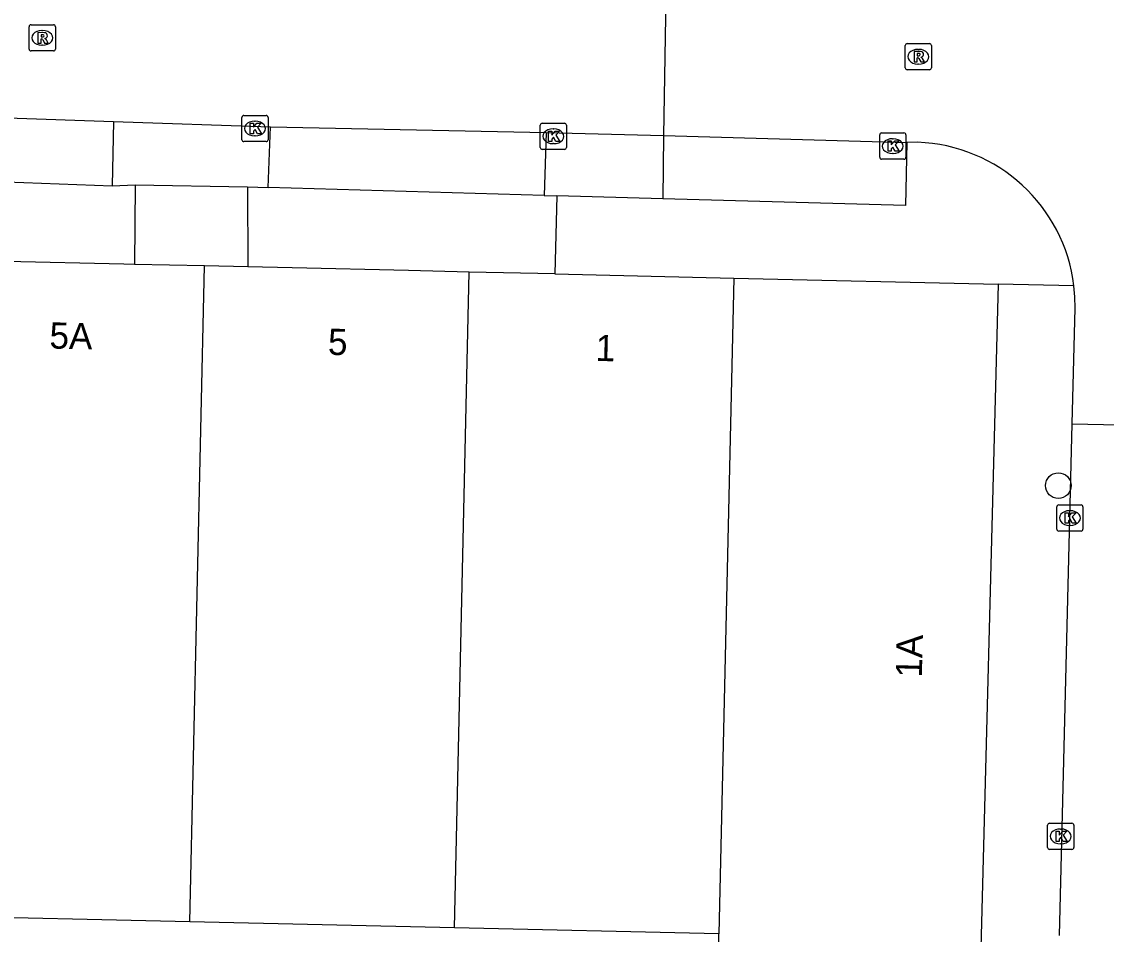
# Model space of a CAD drawing. Extents: x 162082 to 163393, y 388091 to 388632.
# Drawn here: x 162448.47 to 162489.83, y 388163.79 to 388198.6 of the extents above; entities that cross this region are included whole.
import ezdxf

# ---------------------------------------------------------------- set-up
doc = ezdxf.new("R2010")
doc.units = 0
for name, color, linetype in [('IMGEO_Boom', 7, 'Continuous'), ('IMGEO_Kolk', 7, 'Continuous'), ('IMGEO_Pand', 7, 'Continuous'), ('IMGEO_Pand_nummerreeks', 7, 'Continuous'), ('IMGEO_Parkeervlak_open', 7, 'Continuous'), ('IMGEO_Rijbaan_lokaal_open', 7, 'Continuous'), ('IMGEO_Rioolput', 7, 'Continuous'), ('IMGEO_Voetpad_open', 7, 'Continuous')]:
    doc.layers.add(name, color=color, linetype=linetype)

msp = doc.modelspace()

# ---------------------------------------------------------------- linework, layer by layer
at = {"layer": 'IMGEO_Boom'}
msp.add_circle((162488.002, 388180.905), 0.489, dxfattribs=at)
at = {"layer": 'IMGEO_Kolk'}
for p, q in [((162456.863, 388194.101), (162456.863, 388194.953)), ((162456.938, 388195.027), (162457.79, 388195.027)), ((162457.351, 388194.807), (162457.376, 388194.807)), ((162457.864, 388194.953), (162457.864, 388194.101)), ((162468.243, 388193.804), (162468.243, 388194.656)), ((162468.318, 388194.73), (162469.17, 388194.73)), ((162468.731, 388194.51), (162468.756, 388194.51)), ((162469.244, 388194.656), (162469.244, 388193.804)), ((162481.264, 388194.358), (162482.116, 388194.358)), ((162457.79, 388194.027), (162456.938, 388194.027)), ((162457.374, 388194.247), (162457.349, 388194.247)), ((162468.754, 388193.95), (162468.729, 388193.95)), ((162481.189, 388193.432), (162481.189, 388194.284)), ((162481.677, 388194.138), (162481.702, 388194.138)), ((162482.19, 388194.284), (162482.19, 388193.432)), ((162469.17, 388193.73), (162468.318, 388193.73)), ((162481.7, 388193.578), (162481.675, 388193.578)), ((162482.116, 388193.358), (162481.264, 388193.358)), ((162487.942, 388179.242), (162487.942, 388180.094)), ((162488.017, 388180.168), (162488.869, 388180.168)), ((162488.43, 388179.948), (162488.455, 388179.948)), ((162488.943, 388180.094), (162488.943, 388179.242)), ((162488.869, 388179.168), (162488.017, 388179.168)), ((162488.453, 388179.388), (162488.428, 388179.388)), ((162487.595, 388167.099), (162487.595, 388167.951)), ((162487.67, 388168.025), (162488.522, 388168.025)), ((162488.596, 388167.951), (162488.596, 388167.099)), ((162488.083, 388167.805), (162488.108, 388167.805)), ((162488.106, 388167.245), (162488.081, 388167.245)), ((162488.522, 388167.025), (162487.67, 388167.025))]:
    msp.add_line(p, q, dxfattribs=at)
for points in [[(162456.863, 388194.101), (162456.863, 388194.953)], [(162456.938, 388195.027), (162457.79, 388195.027)], [(162457.864, 388194.953), (162457.864, 388194.101)], [(162457.184, 388194.727), (162457.307, 388194.727), (162457.307, 388194.576), (162457.437, 388194.727), (162457.601, 388194.727), (162457.455, 388194.576), (162457.608, 388194.327), (162457.456, 388194.327), (162457.371, 388194.491), (162457.307, 388194.424), (162457.307, 388194.327), (162457.184, 388194.327), (162457.184, 388194.727)], [(162468.243, 388193.804), (162468.243, 388194.656)], [(162468.318, 388194.73), (162469.17, 388194.73)], [(162468.564, 388194.43), (162468.687, 388194.43), (162468.687, 388194.279), (162468.817, 388194.43), (162468.981, 388194.43), (162468.835, 388194.279), (162468.988, 388194.03), (162468.836, 388194.03), (162468.751, 388194.194), (162468.687, 388194.127), (162468.687, 388194.03), (162468.564, 388194.03), (162468.564, 388194.43)], [(162469.244, 388194.656), (162469.244, 388193.804)], [(162481.264, 388194.358), (162482.116, 388194.358)], [(162457.79, 388194.027), (162456.938, 388194.027)], [(162481.189, 388193.432), (162481.189, 388194.284)], [(162481.51, 388194.058), (162481.633, 388194.058), (162481.633, 388193.907), (162481.763, 388194.058), (162481.927, 388194.058), (162481.781, 388193.907), (162481.934, 388193.658), (162481.782, 388193.658), (162481.697, 388193.822), (162481.633, 388193.755), (162481.633, 388193.658), (162481.51, 388193.658), (162481.51, 388194.058)], [(162482.19, 388194.284), (162482.19, 388193.432)], [(162469.17, 388193.73), (162468.318, 388193.73)], [(162482.116, 388193.358), (162481.264, 388193.358)], [(162487.942, 388179.242), (162487.942, 388180.094)], [(162488.017, 388180.168), (162488.869, 388180.168)], [(162488.263, 388179.868), (162488.386, 388179.868), (162488.386, 388179.717), (162488.516, 388179.868), (162488.68, 388179.868), (162488.534, 388179.717), (162488.687, 388179.468), (162488.535, 388179.468), (162488.45, 388179.632), (162488.386, 388179.565), (162488.386, 388179.468), (162488.263, 388179.468), (162488.263, 388179.868)], [(162488.943, 388180.094), (162488.943, 388179.242)], [(162488.869, 388179.168), (162488.017, 388179.168)], [(162487.595, 388167.099), (162487.595, 388167.951)], [(162487.67, 388168.025), (162488.522, 388168.025)], [(162488.596, 388167.951), (162488.596, 388167.099)], [(162487.916, 388167.725), (162488.039, 388167.725), (162488.039, 388167.574), (162488.169, 388167.725), (162488.333, 388167.725), (162488.187, 388167.574), (162488.34, 388167.325), (162488.188, 388167.325), (162488.103, 388167.489), (162488.039, 388167.422), (162488.039, 388167.325), (162487.916, 388167.325), (162487.916, 388167.725)], [(162488.522, 388167.025), (162487.67, 388167.025)]]:
    msp.add_lwpolyline(points, dxfattribs=at)
for centre, start, end in [((162456.94, 388194.951), 91.552, 178.448), ((162456.94, 388194.951), 91.552, 178.448), ((162457.788, 388194.951), 1.552, 88.448), ((162457.788, 388194.951), 1.552, 88.448), ((162468.32, 388194.654), 91.552, 178.448), ((162468.32, 388194.654), 91.552, 178.448), ((162469.168, 388194.654), 1.552, 88.448), ((162469.168, 388194.654), 1.552, 88.448), ((162481.266, 388194.282), 91.552, 178.448), ((162481.266, 388194.282), 91.552, 178.448), ((162482.114, 388194.282), 1.552, 88.448), ((162482.114, 388194.282), 1.552, 88.448), ((162456.94, 388194.103), 181.552, 268.448), ((162456.94, 388194.103), 181.552, 268.448), ((162457.788, 388194.103), 271.552, 358.448), ((162457.788, 388194.103), 271.552, 358.448), ((162468.32, 388193.806), 181.552, 268.448), ((162468.32, 388193.806), 181.552, 268.448), ((162469.168, 388193.806), 271.552, 358.448), ((162469.168, 388193.806), 271.552, 358.448), ((162481.266, 388193.434), 181.552, 268.448), ((162481.266, 388193.434), 181.552, 268.448), ((162482.114, 388193.434), 271.552, 358.448), ((162482.114, 388193.434), 271.552, 358.448), ((162488.019, 388180.092), 91.552, 178.448), ((162488.019, 388180.092), 91.552, 178.448), ((162488.867, 388180.092), 1.552, 88.448), ((162488.867, 388180.092), 1.552, 88.448), ((162488.019, 388179.244), 181.552, 268.448), ((162488.019, 388179.244), 181.552, 268.448), ((162488.867, 388179.244), 271.552, 358.448), ((162488.867, 388179.244), 271.552, 358.448), ((162487.672, 388167.949), 91.552, 178.448), ((162487.672, 388167.949), 91.552, 178.448), ((162488.52, 388167.949), 1.552, 88.448), ((162488.52, 388167.949), 1.552, 88.448), ((162487.672, 388167.101), 181.552, 268.448), ((162487.672, 388167.101), 181.552, 268.448), ((162488.52, 388167.101), 271.552, 358.448), ((162488.52, 388167.101), 271.552, 358.448)]:
    msp.add_arc(centre, 0.0765, start, end, dxfattribs=at)
for centre, major_axis, ratio, start_param, end_param in [((162457.35, 388194.527), (-0.387, 0.002), 0.722429, 4.712389, 7.853982), ((162457.375, 388194.527), (-0.39, 0.002), 0.717154, 1.570796, 4.712389), ((162468.73, 388194.23), (-0.387, 0.002), 0.722429, 4.712389, 7.853982), ((162468.755, 388194.23), (-0.39, 0.002), 0.717154, 1.570796, 4.712389), ((162481.676, 388193.858), (-0.387, 0.002), 0.722429, 4.712389, 7.853982), ((162481.701, 388193.858), (-0.39, 0.002), 0.717154, 1.570796, 4.712389), ((162488.429, 388179.668), (-0.387, 0.002), 0.722429, 4.712389, 7.853982), ((162488.454, 388179.668), (-0.39, 0.002), 0.717154, 1.570796, 4.712389), ((162488.082, 388167.525), (-0.387, 0.002), 0.722429, 4.712389, 7.853982), ((162488.107, 388167.525), (-0.39, 0.002), 0.717154, 1.570796, 4.712389)]:
    msp.add_ellipse(centre, major_axis=major_axis, ratio=ratio, start_param=start_param, end_param=end_param, dxfattribs=at)
at = {"layer": 'IMGEO_Pand'}
for points in [[(162452.771, 388189.344), (162452.361, 388189.353), (162447.872, 388189.456), (162446.871, 388189.479)], [(162455.444, 388189.283), (162452.771, 388189.344)], [(162454.875, 388164.26), (162455.444, 388189.283)], [(162457.091, 388189.245), (162455.444, 388189.283)], [(162465.536, 388189.053), (162463.223, 388189.106), (162458.778, 388189.207), (162457.091, 388189.245)], [(162464.967, 388164.031), (162465.536, 388189.053)], [(162468.797, 388188.979), (162465.536, 388189.053)], [(162468.797, 388188.979), (162475.628, 388188.823)], [(162475.628, 388188.823), (162475.059, 388163.801)], [(162475.628, 388188.823), (162485.703, 388188.593)], [(162485.703, 388188.593), (162484.964, 388159.853)], [(162454.875, 388164.26), (162444.783, 388164.49), (162444.873, 388168.421)], [(162464.967, 388164.031), (162454.875, 388164.26)], [(162475.059, 388163.801), (162464.967, 388164.031)], [(162484.964, 388159.853), (162479.966, 388159.982), (162474.998, 388160.11), (162475.059, 388163.801)]]:
    msp.add_lwpolyline(points, dxfattribs=at)
at = {"layer": 'IMGEO_Parkeervlak_open'}
msp.add_lwpolyline([(162472.938, 388194.261), (162472.925, 388191.851)], dxfattribs=at)
at = {"layer": 'IMGEO_Rijbaan_lokaal_open'}
for points in [[(162473.05, 388200.285), (162472.938, 388194.261)], [(162447.924, 388194.933), (162451.967, 388194.796)], [(162451.967, 388194.796), (162457.958, 388194.586)], [(162457.958, 388194.586), (162468.471, 388194.374)], [(162468.471, 388194.374), (162472.938, 388194.261)], [(162472.938, 388194.261), (162482.226, 388193.997)], [(162482.636, 388194.002), (162482.226, 388193.997)], [(162488.529, 388183.267), (162488.64, 388187.674), (162488.633, 388188.101), (162488.596, 388188.527)], [(162488.051, 388163.748), (162488.529, 388183.267)], [(162488.529, 388183.267), (162494.536, 388183.135)]]:
    msp.add_lwpolyline(points, dxfattribs=at)
msp.add_arc((162482.417, 388187.783), 6.223, 6.8699, 87.9875, dxfattribs=at)
at = {"layer": 'IMGEO_Rioolput'}
for p, q in [((162448.824, 388198.486), (162449.676, 388198.486)), ((162448.749, 388197.56), (162448.749, 388198.412)), ((162449.237, 388198.266), (162449.262, 388198.266)), ((162449.75, 388198.412), (162449.75, 388197.56)), ((162449.26, 388197.706), (162449.235, 388197.706)), ((162482.163, 388196.841), (162482.163, 388197.693)), ((162482.238, 388197.767), (162483.09, 388197.767)), ((162483.164, 388197.693), (162483.164, 388196.841)), ((162449.676, 388197.486), (162448.824, 388197.486)), ((162482.651, 388197.547), (162482.676, 388197.547)), ((162482.674, 388196.987), (162482.649, 388196.987)), ((162483.09, 388196.767), (162482.238, 388196.767))]:
    msp.add_line(p, q, dxfattribs=at)
for points in [[(162448.824, 388198.486), (162449.676, 388198.486)], [(162448.749, 388197.56), (162448.749, 388198.412)], [(162449.338, 388198.184), (162449.086, 388198.186), (162449.086, 388197.786)], [(162449.264, 388198.105), (162449.21, 388198.105), (162449.21, 388198.024)], [(162449.75, 388198.412), (162449.75, 388197.56)], [(162449.086, 388197.786), (162449.21, 388197.786), (162449.21, 388197.948), (162449.221, 388197.948)], [(162449.21, 388198.024), (162449.262, 388198.024)], [(162449.268, 388197.919), (162449.339, 388197.786), (162449.479, 388197.786), (162449.414, 388197.912)], [(162482.163, 388196.841), (162482.163, 388197.693)], [(162482.238, 388197.767), (162483.09, 388197.767)], [(162483.164, 388197.693), (162483.164, 388196.841)], [(162449.676, 388197.486), (162448.824, 388197.486)], [(162482.752, 388197.465), (162482.5, 388197.467), (162482.5, 388197.067)], [(162482.5, 388197.067), (162482.624, 388197.067), (162482.624, 388197.229), (162482.635, 388197.229)], [(162482.678, 388197.386), (162482.624, 388197.386), (162482.624, 388197.305)], [(162482.624, 388197.305), (162482.676, 388197.305)], [(162482.682, 388197.2), (162482.753, 388197.067), (162482.893, 388197.067), (162482.828, 388197.193)], [(162483.09, 388196.767), (162482.238, 388196.767)]]:
    msp.add_lwpolyline(points, dxfattribs=at)
for centre, radius, start, end in [((162448.826, 388198.41), 0.0765, 91.552, 178.448), ((162448.826, 388198.41), 0.0765, 91.552, 178.448), ((162449.674, 388198.41), 0.0765, 1.552, 88.448), ((162449.674, 388198.41), 0.0765, 1.552, 88.448), ((162449.27, 388198.009), 0.0964, 77.0061, 93.1865), ((162449.284, 388198.066), 0.0378, 276.6634, 79.6772), ((162449.337, 388198.074), 0.109, 350.3612, 89.416), ((162449.22, 388197.895), 0.0533, 26.0293, 88.6989), ((162449.246, 388198.213), 0.19, 274.7715, 282.9687), ((162449.335, 388198.074), 0.112, 277.5842, 350.9817), ((162449.319, 388197.859), 0.108, 29.5134, 73.7905), ((162482.24, 388197.691), 0.0765, 91.552, 178.448), ((162482.24, 388197.691), 0.0765, 91.552, 178.448), ((162483.088, 388197.691), 0.0765, 1.552, 88.448), ((162483.088, 388197.691), 0.0765, 1.552, 88.448), ((162448.826, 388197.562), 0.0765, 181.552, 268.448), ((162448.826, 388197.562), 0.0765, 181.552, 268.448), ((162449.674, 388197.562), 0.0765, 271.552, 358.448), ((162449.674, 388197.562), 0.0765, 271.552, 358.448), ((162482.634, 388197.176), 0.0533, 26.0293, 88.6989), ((162482.66, 388197.494), 0.19, 274.7715, 282.9687), ((162482.684, 388197.29), 0.0964, 77.0061, 93.1865), ((162482.698, 388197.347), 0.0378, 276.6634, 79.6772), ((162482.751, 388197.355), 0.109, 350.3612, 89.416), ((162482.749, 388197.355), 0.112, 277.5842, 350.9817), ((162482.733, 388197.14), 0.108, 29.5134, 73.7905), ((162482.24, 388196.843), 0.0765, 181.552, 268.448), ((162482.24, 388196.843), 0.0765, 181.552, 268.448), ((162483.088, 388196.843), 0.0765, 271.552, 358.448), ((162483.088, 388196.843), 0.0765, 271.552, 358.448)]:
    msp.add_arc(centre, radius, start, end, dxfattribs=at)
for centre, major_axis, ratio, start_param, end_param in [((162449.236, 388197.986), (-0.387, 0.002), 0.722429, 4.712389, 7.853982), ((162449.261, 388197.986), (-0.39, 0.002), 0.717154, 1.570796, 4.712389), ((162482.65, 388197.267), (-0.387, 0.002), 0.722429, 4.712389, 7.853982), ((162482.675, 388197.267), (-0.39, 0.002), 0.717154, 1.570796, 4.712389)]:
    msp.add_ellipse(centre, major_axis=major_axis, ratio=ratio, start_param=start_param, end_param=end_param, dxfattribs=at)
at = {"layer": 'IMGEO_Voetpad_open'}
for points in [[(162451.967, 388194.796), (162451.922, 388192.347)], [(162457.872, 388192.28), (162457.958, 388194.586)], [(162468.471, 388194.374), (162468.393, 388191.974)], [(162482.226, 388193.997), (162482.177, 388191.595), (162472.925, 388191.851)], [(162447.869, 388192.495), (162451.922, 388192.347)], [(162451.922, 388192.347), (162452.796, 388192.376)], [(162452.796, 388192.376), (162452.771, 388189.344)], [(162452.796, 388192.376), (162457.075, 388192.299)], [(162457.075, 388192.299), (162457.091, 388189.245)], [(162457.075, 388192.299), (162457.872, 388192.28)], [(162468.393, 388191.974), (162457.872, 388192.28)], [(162468.393, 388191.974), (162468.876, 388191.961)], [(162468.876, 388191.961), (162468.797, 388188.979)], [(162472.925, 388191.851), (162468.876, 388191.961)], [(162488.596, 388188.527), (162485.703, 388188.593)]]:
    msp.add_lwpolyline(points, dxfattribs=at)

# ---------------------------------------------------------------- texts
at = {"layer": 'IMGEO_Pand_nummerreeks'}
for s, rotation, p in [('5A', 358.6937, (162449.519, 388186.137)), ('5', 358.6944, (162460.14, 388185.896)), ('1', 358.6944, (162470.346, 388185.663)), ('1A', 88.5271, (162482.796, 388173.575))]:
    msp.add_text(s, height=1, rotation=rotation, dxfattribs=at).set_placement(p)

doc.saveas('drawing.dxf')
